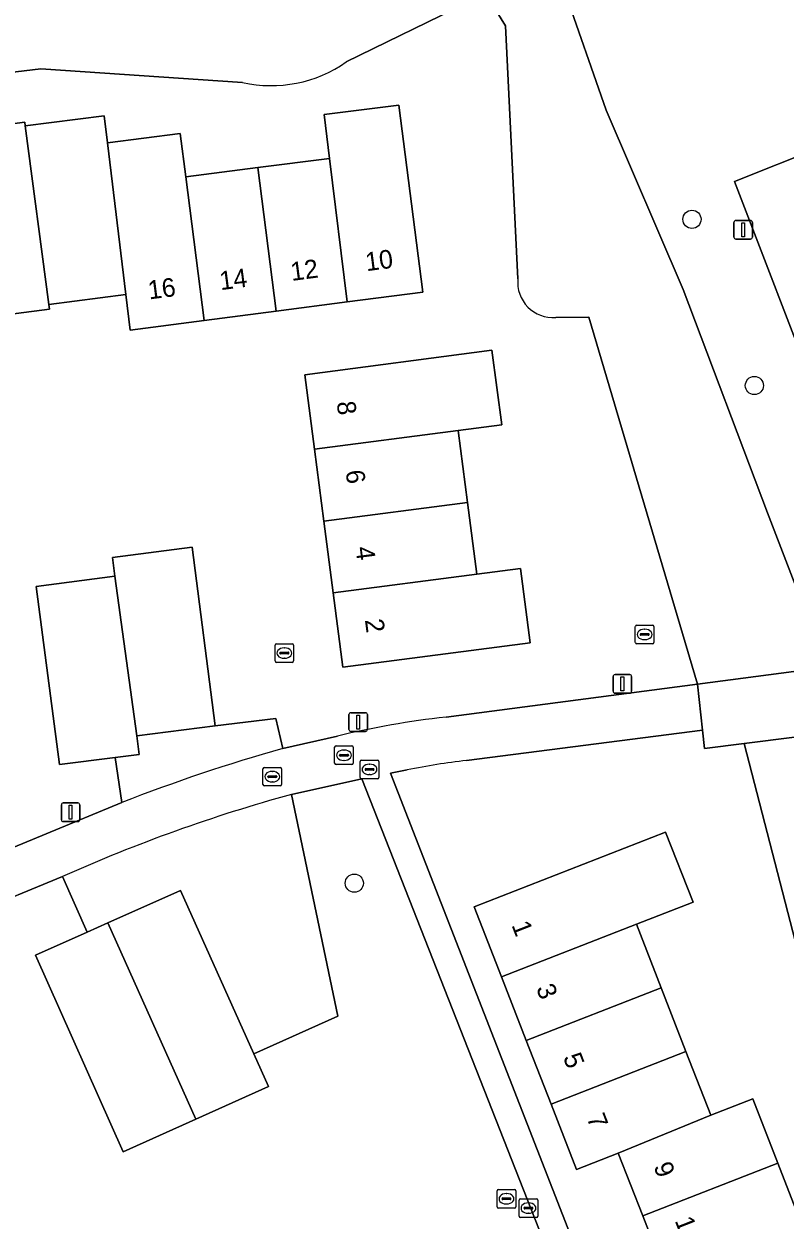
# Model space of a CAD drawing. Extents: x 159451 to 160664, y 388402 to 389723.
# Drawn here: x 159545.2 to 159586.1, y 389229 to 389293.3 of the extents above; entities that cross this region are included whole.
import ezdxf

# ---------------------------------------------------------------- set-up
doc = ezdxf.new("R2010")
doc.units = 0
for name, color, linetype in [('IMGEO_Boom', 7, 'Continuous'), ('IMGEO_Bouwland', 7, 'Continuous'), ('IMGEO_Groenvoorziening', 7, 'Continuous'), ('IMGEO_Lichtmast', 7, 'Continuous'), ('IMGEO_Meer_plas_ven_vijver', 7, 'Continuous'), ('IMGEO_Pand', 7, 'Continuous'), ('IMGEO_Pand_nummerreeks', 7, 'Continuous'), ('IMGEO_Parkeervlak_halfverhard', 7, 'Continuous'), ('IMGEO_Rijbaan_lokaal_gesloten', 7, 'Continuous'), ('IMGEO_Rijbaan_lokaal_halfverhard', 7, 'Continuous'), ('IMGEO_Rioolput', 7, 'Continuous')]:
    doc.layers.add(name, color=color, linetype=linetype)

msp = doc.modelspace()

# ---------------------------------------------------------------- linework, layer by layer
at = {"layer": 'IMGEO_Boom'}
for centre in [(159581.107, 389282.768), (159584.465, 389273.835), (159562.963, 389247.093)]:
    msp.add_circle(centre, 0.489, dxfattribs=at)
at = {"layer": 'IMGEO_Bouwland'}
for points in [[(159590.332, 389238.414), (159588.958, 389238.151), (159588.252, 389238.537), (159587.915, 389239.139), (159583.906, 389254.592), (159581.78, 389254.325), (159581.675, 389255.309), (159568.993, 389253.682)], [(159580.373, 389208.403), (159573.107, 389227.927), (159563.374, 389252.707), (159559.597, 389251.864), (159562.085, 389239.938), (159557.562, 389237.923), (159558.351, 389236.161), (159554.447, 389234.413), (159550.543, 389232.664), (159545.842, 389243.23), (159548.614, 389244.465), (159547.283, 389247.447), (159522.997, 389237.416), (159523.334, 389236.494), (159515.988, 389233.475), (159514.682, 389236.714), (159522.027, 389239.718), (159536.816, 389245.805), (159535.285, 389249.699)], [(159565.813, 389253.186), (159564.916, 389253.004), (159575.523, 389225.793), (159580.698, 389211.752)]]:
    msp.add_lwpolyline(points, dxfattribs=at)
msp.add_lwpolyline([(159585.725, 389232.05), (159587.076, 389228.593), (159588.427, 389225.136), (159591.484, 389226.33), (159592.944, 389222.587), (159582.637, 389218.552), (159581.17, 389222.301), (159579.818, 389225.756), (159578.465, 389229.213), (159577.145, 389232.586), (159574.908, 389231.714), (159573.541, 389235.222), (159572.208, 389238.644), (159570.876, 389242.061), (159569.411, 389245.821), (159579.696, 389249.831), (159581.176, 389246.078), (159578.122, 389244.887), (159579.454, 389241.465), (159580.787, 389238.042), (159582.119, 389234.62), (159584.374, 389235.507)], close=True, dxfattribs=at)
msp.add_arc((159573.115, 389216.814), 37.098, 96.37912, 101.35142, dxfattribs=at)
at = {"layer": 'IMGEO_Groenvoorziening'}
for points in [[(159574.217, 389295.171), (159576.492, 389288.625), (159580.643, 389278.999), (159585.177, 389266.997), (159588.35, 389258.709)], [(159571.755, 389279.564), (159571.085, 389293.162), (159570.386, 389294.298), (159569.066, 389294.418), (159562.535, 389291.222)], [(159556.966, 389290.126), (159546.129, 389290.863), (159532.239, 389289.197)], [(159541.295, 389287.473), (159545.256, 389287.981), (159545.281, 389287.787), (159549.518, 389288.329), (159549.707, 389286.878), (159553.612, 389287.385), (159553.913, 389285.047), (159557.776, 389285.546), (159561.639, 389286.044), (159561.351, 389288.395), (159565.365, 389288.906), (159566.652, 389278.858), (159562.584, 389278.33), (159558.771, 389277.834), (159554.906, 389277.332), (159550.926, 389276.815), (159550.68, 389278.733), (159546.558, 389278.199), (159546.592, 389277.935), (159542.577, 389277.414)], [(159587.925, 389273.015), (159583.387, 389284.803), (159588.068, 389286.657)], [(159567.894, 389256.022), (159581.411, 389257.784), (159575.559, 389277.502), (159573.786, 389277.496)], [(159537.657, 389247.809), (159538.251, 389246.377), (159550.467, 389251.425), (159550.122, 389253.843), (159547.128, 389253.464), (159545.873, 389263.038), (159550.103, 389263.588), (159549.974, 389264.586), (159554.246, 389265.142), (159555.492, 389255.556), (159558.754, 389255.947), (159559.116, 389254.331), (159562.054, 389254.997)]]:
    msp.add_lwpolyline(points, dxfattribs=at)
msp.add_lwpolyline([(159570.891, 389271.725), (159568.539, 389271.414), (159569.046, 389267.555), (159569.552, 389263.705), (159571.892, 389264.011), (159572.415, 389260.004), (159562.352, 389258.693), (159561.831, 389262.703), (159561.332, 389266.553), (159560.83, 389270.413), (159560.311, 389274.413), (159570.362, 389275.731)], close=True, dxfattribs=at)
for centre, radius, start, end in [((159558.519, 389296.933), 6.981, 257.14877, 305.1187), ((159573.634, 389279.378), 1.888, 174.357, 274.60866), ((159573.278, 389208.199), 48.125, 96.42296, 103.48665)]:
    msp.add_arc(centre, radius, start, end, dxfattribs=at)
at = {"layer": 'IMGEO_Lichtmast'}
for p, q in [((159583.368, 389281.803), (159583.368, 389282.603)), ((159583.368, 389282.603), (159583.368, 389281.803)), ((159583.468, 389282.703), (159584.258, 389282.703)), ((159584.258, 389282.703), (159583.468, 389282.703)), ((159584.358, 389282.603), (159584.358, 389281.803)), ((159584.358, 389281.803), (159584.358, 389282.603)), ((159584.258, 389281.703), (159583.468, 389281.703)), ((159583.468, 389281.703), (159584.258, 389281.703)), ((159576.874, 389257.405), (159576.874, 389258.205)), ((159576.874, 389258.205), (159576.874, 389257.405)), ((159576.974, 389258.305), (159577.764, 389258.305)), ((159577.764, 389258.305), (159576.974, 389258.305)), ((159577.864, 389258.205), (159577.864, 389257.405)), ((159577.864, 389257.405), (159577.864, 389258.205)), ((159577.764, 389257.305), (159576.974, 389257.305)), ((159576.974, 389257.305), (159577.764, 389257.305)), ((159562.679, 389255.352), (159562.679, 389256.152)), ((159562.679, 389256.152), (159562.679, 389255.352)), ((159562.779, 389256.252), (159563.569, 389256.252)), ((159563.569, 389256.252), (159562.779, 389256.252)), ((159563.669, 389256.152), (159563.669, 389255.352)), ((159563.669, 389255.352), (159563.669, 389256.152)), ((159563.569, 389255.252), (159562.779, 389255.252)), ((159562.779, 389255.252), (159563.569, 389255.252)), ((159547.225, 389250.504), (159547.225, 389251.304)), ((159547.225, 389251.304), (159547.225, 389250.504)), ((159547.325, 389251.404), (159548.115, 389251.404)), ((159548.115, 389251.404), (159547.325, 389251.404)), ((159548.215, 389251.304), (159548.215, 389250.504)), ((159548.215, 389250.504), (159548.215, 389251.304)), ((159548.115, 389250.404), (159547.325, 389250.404)), ((159547.325, 389250.404), (159548.115, 389250.404))]:
    msp.add_line(p, q, dxfattribs=at)
for points in [[(159583.788, 389282.578), (159583.938, 389282.578), (159583.938, 389281.828), (159583.788, 389281.828), (159583.788, 389282.578)], [(159577.294, 389258.18), (159577.444, 389258.18), (159577.444, 389257.43), (159577.294, 389257.43), (159577.294, 389258.18)], [(159563.099, 389256.127), (159563.249, 389256.127), (159563.249, 389255.377), (159563.099, 389255.377), (159563.099, 389256.127)], [(159547.645, 389251.279), (159547.795, 389251.279), (159547.795, 389250.529), (159547.645, 389250.529), (159547.645, 389251.279)]]:
    msp.add_lwpolyline(points, dxfattribs=at)
for centre, start, end in [((159583.468, 389282.603), 90, 180), ((159583.468, 389282.603), 90, 180), ((159584.258, 389282.603), 0, 90), ((159584.258, 389282.603), 360, 90), ((159583.468, 389281.803), 180, 270), ((159583.468, 389281.803), 180, 270), ((159584.258, 389281.803), 270, 0), ((159584.258, 389281.803), 270, 0), ((159576.974, 389258.205), 90, 180), ((159576.974, 389258.205), 90, 180), ((159577.764, 389258.205), 0, 90), ((159577.764, 389258.205), 360, 90), ((159576.974, 389257.405), 180, 270), ((159576.974, 389257.405), 180, 270), ((159577.764, 389257.405), 270, 0), ((159577.764, 389257.405), 270, 0), ((159562.779, 389256.152), 90, 180), ((159562.779, 389256.152), 90, 180), ((159563.569, 389256.152), 0, 90), ((159563.569, 389256.152), 360, 90), ((159562.779, 389255.352), 180, 270), ((159562.779, 389255.352), 180, 270), ((159563.569, 389255.352), 270, 0), ((159563.569, 389255.352), 270, 0), ((159547.325, 389251.304), 90, 180), ((159547.325, 389251.304), 90, 180), ((159548.115, 389251.304), 0, 90), ((159548.115, 389251.304), 360, 90), ((159547.325, 389250.504), 180, 270), ((159547.325, 389250.504), 180, 270), ((159548.115, 389250.504), 270, 0), ((159548.115, 389250.504), 270, 0)]:
    msp.add_arc(centre, 0.1, start, end, dxfattribs=at)
at = {"layer": 'IMGEO_Meer_plas_ven_vijver'}
for points in [[(159581.411, 389257.784), (159588.35, 389258.709), (159585.177, 389266.997), (159580.643, 389278.999), (159576.492, 389288.625), (159574.217, 389295.171)], [(159562.535, 389291.222), (159569.066, 389294.418), (159570.386, 389294.298), (159571.085, 389293.162), (159571.755, 389279.564)], [(159532.239, 389289.197), (159546.129, 389290.863), (159556.966, 389290.126)], [(159573.786, 389277.496), (159575.559, 389277.502), (159581.411, 389257.784)], [(159589.472, 389255.292), (159583.906, 389254.592), (159587.915, 389239.139), (159588.252, 389238.537), (159588.958, 389238.151), (159590.332, 389238.414), (159596.055, 389223.424)]]:
    msp.add_lwpolyline(points, dxfattribs=at)
for centre, radius, start, end in [((159558.519, 389296.933), 6.981, 257.14877, 305.1187), ((159573.634, 389279.378), 1.888, 174.357, 274.60866)]:
    msp.add_arc(centre, radius, start, end, dxfattribs=at)
at = {"layer": 'IMGEO_Pand'}
for points in [[(159565.365, 389288.906), (159561.351, 389288.395), (159561.639, 389286.044), (159562.584, 389278.33), (159566.652, 389278.858)], [(159545.281, 389287.787), (159545.256, 389287.981), (159541.295, 389287.473), (159541.594, 389285.127), (159542.577, 389277.414), (159546.592, 389277.935), (159546.558, 389278.199)], [(159549.707, 389286.878), (159549.518, 389288.329), (159545.281, 389287.787), (159546.558, 389278.199), (159550.68, 389278.733)], [(159553.913, 389285.047), (159553.612, 389287.385), (159549.707, 389286.878), (159550.68, 389278.733), (159550.926, 389276.815), (159554.906, 389277.332)], [(159561.639, 389286.044), (159557.776, 389285.546), (159558.771, 389277.834), (159562.584, 389278.33)], [(159557.776, 389285.546), (159553.913, 389285.047), (159554.906, 389277.332), (159558.771, 389277.834)], [(159570.362, 389275.731), (159560.311, 389274.413), (159560.83, 389270.413), (159568.539, 389271.414), (159570.891, 389271.725)], [(159568.539, 389271.414), (159560.83, 389270.413), (159561.332, 389266.553), (159569.046, 389267.555)], [(159569.046, 389267.555), (159561.332, 389266.553), (159561.831, 389262.703), (159569.552, 389263.705)], [(159554.246, 389265.142), (159549.974, 389264.586), (159550.103, 389263.588), (159551.271, 389255.006), (159555.492, 389255.556)], [(159550.103, 389263.588), (159545.873, 389263.038), (159547.128, 389253.464), (159550.122, 389253.843), (159551.405, 389254.005), (159551.271, 389255.006)], [(159571.892, 389264.011), (159569.552, 389263.705), (159561.831, 389262.703), (159562.352, 389258.693), (159572.415, 389260.004)], [(159581.176, 389246.078), (159579.696, 389249.831), (159569.411, 389245.821), (159570.876, 389242.061), (159578.122, 389244.887)], [(159553.631, 389246.699), (159549.724, 389244.959), (159554.447, 389234.413), (159558.351, 389236.161), (159557.562, 389237.923)], [(159549.724, 389244.959), (159548.614, 389244.465), (159545.842, 389243.23), (159550.543, 389232.664), (159554.447, 389234.413)], [(159579.454, 389241.465), (159578.122, 389244.887), (159570.876, 389242.061), (159572.208, 389238.644)], [(159580.787, 389238.042), (159579.454, 389241.465), (159572.208, 389238.644), (159573.541, 389235.222)], [(159582.119, 389234.62), (159580.787, 389238.042), (159573.541, 389235.222), (159574.908, 389231.714), (159577.145, 389232.586)], [(159585.725, 389232.05), (159584.374, 389235.507), (159582.119, 389234.62), (159577.145, 389232.586), (159578.465, 389229.213)], [(159585.725, 389232.05), (159578.465, 389229.213), (159579.818, 389225.756), (159587.076, 389228.593)]]:
    msp.add_lwpolyline(points, close=True, dxfattribs=at)
at = {"layer": 'IMGEO_Parkeervlak_halfverhard'}
msp.add_lwpolyline([(159588.068, 389286.657), (159583.387, 389284.803), (159587.925, 389273.015), (159592.686, 389274.813)], close=True, dxfattribs=at)
at = {"layer": 'IMGEO_Rijbaan_lokaal_gesloten'}
msp.add_lwpolyline([(159588.35, 389258.709), (159581.411, 389257.784), (159581.675, 389255.309), (159581.78, 389254.325), (159583.906, 389254.592), (159589.472, 389255.292), (159589.73, 389255.325)], close=True, dxfattribs=at)
for points in [[(159568.993, 389253.682), (159581.675, 389255.309), (159581.411, 389257.784), (159567.894, 389256.022)], [(159562.054, 389254.997), (159559.116, 389254.331)], [(159559.597, 389251.864), (159563.374, 389252.707), (159573.107, 389227.927), (159580.373, 389208.403)], [(159580.698, 389211.752), (159575.523, 389225.793), (159564.916, 389253.004), (159565.813, 389253.186)], [(159550.467, 389251.425), (159538.251, 389246.377), (159537.657, 389247.809)], [(159535.285, 389249.699), (159536.816, 389245.805), (159522.027, 389239.718), (159522.997, 389237.416), (159547.283, 389247.447)]]:
    msp.add_lwpolyline(points, dxfattribs=at)
for centre, radius, start, end in [((159573.278, 389208.199), 48.125, 96.42296, 103.48665), ((159584.912, 389163.233), 94.68, 105.81014, 111.33379), ((159573.115, 389216.814), 37.098, 96.37912, 101.35142), ((159582.261, 389169.306), 85.612, 105.35087, 114.11468)]:
    msp.add_arc(centre, radius, start, end, dxfattribs=at)
at = {"layer": 'IMGEO_Rijbaan_lokaal_halfverhard'}
for points in [[(159559.116, 389254.331), (159558.754, 389255.947), (159555.492, 389255.556), (159551.271, 389255.006), (159551.405, 389254.005), (159550.122, 389253.843), (159550.467, 389251.425)], [(159547.283, 389247.447), (159548.614, 389244.465), (159549.724, 389244.959), (159553.631, 389246.699), (159557.562, 389237.923), (159562.085, 389239.938), (159559.597, 389251.864)]]:
    msp.add_lwpolyline(points, dxfattribs=at)
for centre, radius, start, end in [((159584.912, 389163.233), 94.68, 105.81014, 111.33379), ((159582.261, 389169.306), 85.612, 105.35087, 114.11468)]:
    msp.add_arc(centre, radius, start, end, dxfattribs=at)
at = {"layer": 'IMGEO_Rioolput'}
for p, q in [((159578.141, 389260.959), (159578.993, 389260.959)), ((159578.066, 389260.033), (159578.066, 389260.885)), ((159578.325, 389260.453), (159578.325, 389260.465)), ((159578.763, 389260.416), (159578.365, 389260.416)), ((159578.368, 389260.502), (159578.766, 389260.502)), ((159578.554, 389260.739), (159578.579, 389260.739)), ((159578.809, 389260.465), (159578.809, 389260.453)), ((159579.067, 389260.885), (159579.067, 389260.033)), ((159558.705, 389259.033), (159558.705, 389259.885)), ((159558.78, 389259.959), (159559.632, 389259.959)), ((159559.193, 389259.739), (159559.218, 389259.739)), ((159559.706, 389259.885), (159559.706, 389259.033)), ((159578.993, 389259.959), (159578.141, 389259.959)), ((159578.577, 389260.179), (159578.552, 389260.179)), ((159558.964, 389259.453), (159558.964, 389259.465)), ((159559.402, 389259.416), (159559.004, 389259.416)), ((159559.007, 389259.502), (159559.405, 389259.502)), ((159559.216, 389259.179), (159559.191, 389259.179)), ((159559.448, 389259.465), (159559.448, 389259.453)), ((159559.632, 389258.959), (159558.78, 389258.959)), ((159561.908, 389253.543), (159561.908, 389254.395)), ((159561.983, 389254.469), (159562.835, 389254.469)), ((159562.167, 389253.963), (159562.167, 389253.975)), ((159562.605, 389253.926), (159562.207, 389253.926)), ((159562.21, 389254.012), (159562.608, 389254.012)), ((159562.396, 389254.249), (159562.421, 389254.249)), ((159562.651, 389253.975), (159562.651, 389253.963)), ((159562.909, 389254.395), (159562.909, 389253.543)), ((159558.058, 389252.391), (159558.058, 389253.243)), ((159558.133, 389253.317), (159558.985, 389253.317)), ((159559.059, 389253.243), (159559.059, 389252.391)), ((159562.835, 389253.469), (159561.983, 389253.469)), ((159562.419, 389253.689), (159562.394, 389253.689)), ((159563.282, 389252.779), (159563.282, 389253.631)), ((159563.357, 389253.705), (159564.209, 389253.705)), ((159563.541, 389253.199), (159563.541, 389253.211)), ((159563.584, 389253.248), (159563.982, 389253.248)), ((159563.77, 389253.485), (159563.795, 389253.485)), ((159564.025, 389253.211), (159564.025, 389253.199)), ((159564.283, 389253.631), (159564.283, 389252.779)), ((159558.317, 389252.811), (159558.317, 389252.823)), ((159558.755, 389252.774), (159558.357, 389252.774)), ((159558.36, 389252.86), (159558.758, 389252.86)), ((159558.546, 389253.097), (159558.571, 389253.097)), ((159558.801, 389252.823), (159558.801, 389252.811)), ((159564.209, 389252.705), (159563.357, 389252.705)), ((159563.979, 389253.162), (159563.581, 389253.162)), ((159563.793, 389252.925), (159563.768, 389252.925)), ((159558.985, 389252.317), (159558.133, 389252.317)), ((159558.569, 389252.537), (159558.544, 389252.537)), ((159570.642, 389229.707), (159570.642, 389230.559)), ((159570.717, 389230.633), (159571.569, 389230.633)), ((159570.901, 389230.127), (159570.901, 389230.139)), ((159571.339, 389230.09), (159570.941, 389230.09)), ((159570.944, 389230.176), (159571.342, 389230.176)), ((159571.13, 389230.413), (159571.155, 389230.413)), ((159571.385, 389230.139), (159571.385, 389230.127)), ((159571.643, 389230.559), (159571.643, 389229.707)), ((159571.823, 389229.206), (159571.823, 389230.058)), ((159571.898, 389230.132), (159572.75, 389230.132)), ((159572.824, 389230.058), (159572.824, 389229.206)), ((159571.569, 389229.633), (159570.717, 389229.633)), ((159571.153, 389229.853), (159571.128, 389229.853)), ((159572.082, 389229.626), (159572.082, 389229.638)), ((159572.52, 389229.589), (159572.122, 389229.589)), ((159572.125, 389229.675), (159572.523, 389229.675)), ((159572.311, 389229.912), (159572.336, 389229.912)), ((159572.566, 389229.638), (159572.566, 389229.626)), ((159572.75, 389229.132), (159571.898, 389229.132)), ((159572.334, 389229.352), (159572.309, 389229.352))]:
    msp.add_line(p, q, dxfattribs=at)
for points in [[(159578.141, 389260.959), (159578.993, 389260.959)], [(159578.066, 389260.033), (159578.066, 389260.885)], [(159579.067, 389260.885), (159579.067, 389260.033)], [(159558.705, 389259.033), (159558.705, 389259.885)], [(159558.78, 389259.959), (159559.632, 389259.959)], [(159559.706, 389259.885), (159559.706, 389259.033)], [(159578.993, 389259.959), (159578.141, 389259.959)], [(159559.632, 389258.959), (159558.78, 389258.959)], [(159561.908, 389253.543), (159561.908, 389254.395)], [(159561.983, 389254.469), (159562.835, 389254.469)], [(159562.909, 389254.395), (159562.909, 389253.543)], [(159558.058, 389252.391), (159558.058, 389253.243)], [(159558.133, 389253.317), (159558.985, 389253.317)], [(159559.059, 389253.243), (159559.059, 389252.391)], [(159562.835, 389253.469), (159561.983, 389253.469)], [(159563.282, 389252.779), (159563.282, 389253.631)], [(159563.357, 389253.705), (159564.209, 389253.705)], [(159564.283, 389253.631), (159564.283, 389252.779)], [(159564.209, 389252.705), (159563.357, 389252.705)], [(159558.985, 389252.317), (159558.133, 389252.317)], [(159570.642, 389229.707), (159570.642, 389230.559)], [(159570.717, 389230.633), (159571.569, 389230.633)], [(159571.643, 389230.559), (159571.643, 389229.707)], [(159571.823, 389229.206), (159571.823, 389230.058)], [(159571.898, 389230.132), (159572.75, 389230.132)], [(159572.824, 389230.058), (159572.824, 389229.206)], [(159571.569, 389229.633), (159570.717, 389229.633)], [(159572.75, 389229.132), (159571.898, 389229.132)]]:
    msp.add_lwpolyline(points, dxfattribs=at)
for centre, radius, start, end in [((159578.143, 389260.883), 0.0765, 91.55205, 178.44795), ((159578.143, 389260.883), 0.0765, 91.55205, 178.44795), ((159578.991, 389260.883), 0.0765, 1.55205, 88.44795), ((159578.991, 389260.883), 0.0765, 1.55205, 88.44795), ((159578.365, 389260.462), 0.0403, 85.87752, 175.75265), ((159578.362, 389260.452), 0.0366, 178.93798, 274.71019), ((159578.766, 389260.459), 0.043, 264.86636, 352.45326), ((159578.77, 389260.464), 0.0386, 1.73085, 96.63898), ((159558.782, 389259.883), 0.0765, 91.55205, 178.44795), ((159558.782, 389259.883), 0.0765, 91.55205, 178.44795), ((159559.63, 389259.883), 0.0765, 1.55205, 88.44795), ((159559.63, 389259.883), 0.0765, 1.55205, 88.44795), ((159578.143, 389260.035), 0.0765, 181.55205, 268.44795), ((159578.143, 389260.035), 0.0765, 181.55205, 268.44795), ((159578.991, 389260.035), 0.0765, 271.55205, 358.44795), ((159578.991, 389260.035), 0.0765, 271.55205, 358.44795), ((159558.782, 389259.035), 0.0765, 181.55205, 268.44795), ((159558.782, 389259.035), 0.0765, 181.55205, 268.44795), ((159559.004, 389259.462), 0.0403, 85.87752, 175.75265), ((159559.001, 389259.452), 0.0366, 178.93798, 274.71019), ((159559.405, 389259.459), 0.043, 264.86636, 352.45326), ((159559.409, 389259.464), 0.0386, 1.73085, 96.63898), ((159559.63, 389259.035), 0.0765, 271.55205, 358.44795), ((159559.63, 389259.035), 0.0765, 271.55205, 358.44795), ((159561.985, 389254.393), 0.0765, 91.55205, 178.44795), ((159561.985, 389254.393), 0.0765, 91.55205, 178.44795), ((159562.207, 389253.972), 0.0403, 85.87752, 175.75265), ((159562.204, 389253.962), 0.0366, 178.93798, 274.71019), ((159562.608, 389253.969), 0.043, 264.86636, 352.45326), ((159562.612, 389253.974), 0.0386, 1.73085, 96.63898), ((159562.833, 389254.393), 0.0765, 1.55205, 88.44795), ((159562.833, 389254.393), 0.0765, 1.55205, 88.44795), ((159558.135, 389253.241), 0.0765, 91.55205, 178.44795), ((159558.135, 389253.241), 0.0765, 91.55205, 178.44795), ((159558.983, 389253.241), 0.0765, 1.55205, 88.44795), ((159558.983, 389253.241), 0.0765, 1.55205, 88.44795), ((159561.985, 389253.545), 0.0765, 181.55205, 268.44795), ((159561.985, 389253.545), 0.0765, 181.55205, 268.44795), ((159562.833, 389253.545), 0.0765, 271.55205, 358.44795), ((159562.833, 389253.545), 0.0765, 271.55205, 358.44795), ((159563.359, 389253.629), 0.0765, 91.55205, 178.44795), ((159563.359, 389253.629), 0.0765, 91.55205, 178.44795), ((159563.581, 389253.208), 0.0403, 85.87752, 175.75265), ((159563.578, 389253.198), 0.0366, 178.93798, 274.71019), ((159563.982, 389253.205), 0.043, 264.86636, 352.45326), ((159563.986, 389253.21), 0.0386, 1.73085, 96.63898), ((159564.207, 389253.629), 0.0765, 1.55205, 88.44795), ((159564.207, 389253.629), 0.0765, 1.55205, 88.44795), ((159558.357, 389252.82), 0.0403, 85.87752, 175.75265), ((159558.354, 389252.81), 0.0366, 178.93798, 274.71019), ((159558.758, 389252.817), 0.043, 264.86636, 352.45326), ((159558.762, 389252.822), 0.0386, 1.73085, 96.63898), ((159563.359, 389252.781), 0.0765, 181.55205, 268.44795), ((159563.359, 389252.781), 0.0765, 181.55205, 268.44795), ((159564.207, 389252.781), 0.0765, 271.55205, 358.44795), ((159564.207, 389252.781), 0.0765, 271.55205, 358.44795), ((159558.135, 389252.393), 0.0765, 181.55205, 268.44795), ((159558.135, 389252.393), 0.0765, 181.55205, 268.44795), ((159558.983, 389252.393), 0.0765, 271.55205, 358.44795), ((159558.983, 389252.393), 0.0765, 271.55205, 358.44795), ((159570.719, 389230.557), 0.0765, 91.55205, 178.44795), ((159570.719, 389230.557), 0.0765, 91.55205, 178.44795), ((159570.941, 389230.136), 0.0403, 85.87752, 175.75265), ((159570.938, 389230.126), 0.0366, 178.93798, 274.71019), ((159571.342, 389230.133), 0.043, 264.86636, 352.45326), ((159571.346, 389230.138), 0.0386, 1.73085, 96.63898), ((159571.567, 389230.557), 0.0765, 1.55205, 88.44795), ((159571.567, 389230.557), 0.0765, 1.55205, 88.44795), ((159571.9, 389230.056), 0.0765, 91.55205, 178.44795), ((159571.9, 389230.056), 0.0765, 91.55205, 178.44795), ((159572.748, 389230.056), 0.0765, 1.55205, 88.44795), ((159572.748, 389230.056), 0.0765, 1.55205, 88.44795), ((159570.719, 389229.709), 0.0765, 181.55205, 268.44795), ((159570.719, 389229.709), 0.0765, 181.55205, 268.44795), ((159571.567, 389229.709), 0.0765, 271.55205, 358.44795), ((159571.567, 389229.709), 0.0765, 271.55205, 358.44795), ((159572.122, 389229.635), 0.0403, 85.87752, 175.75265), ((159572.119, 389229.625), 0.0366, 178.93798, 274.71019), ((159572.523, 389229.632), 0.043, 264.86636, 352.45326), ((159572.527, 389229.637), 0.0386, 1.73085, 96.63898), ((159571.9, 389229.208), 0.0765, 181.55205, 268.44795), ((159571.9, 389229.208), 0.0765, 181.55205, 268.44795), ((159572.748, 389229.208), 0.0765, 271.55205, 358.44795), ((159572.748, 389229.208), 0.0765, 271.55205, 358.44795)]:
    msp.add_arc(centre, radius, start, end, dxfattribs=at)
for centre, major_axis, ratio, start_param, end_param in [((159578.553, 389260.459), (-0.387, 0.002), 0.722429, 4.712389, 7.853982), ((159578.578, 389260.459), (-0.39, 0.002), 0.717154, 1.570796, 4.712389), ((159559.192, 389259.459), (-0.387, 0.002), 0.722429, 4.712389, 7.853982), ((159559.217, 389259.459), (-0.39, 0.002), 0.717154, 1.570796, 4.712389), ((159562.395, 389253.969), (-0.387, 0.002), 0.722429, 4.712389, 7.853982), ((159562.42, 389253.969), (-0.39, 0.002), 0.717154, 1.570796, 4.712389), ((159563.769, 389253.205), (-0.387, 0.002), 0.722429, 4.712389, 7.853982), ((159563.794, 389253.205), (-0.39, 0.002), 0.717154, 1.570796, 4.712389), ((159558.545, 389252.817), (-0.387, 0.002), 0.722429, 4.712389, 7.853982), ((159558.57, 389252.817), (-0.39, 0.002), 0.717154, 1.570796, 4.712389), ((159571.129, 389230.133), (-0.387, 0.002), 0.722429, 4.712389, 7.853982), ((159571.154, 389230.133), (-0.39, 0.002), 0.717154, 1.570796, 4.712389), ((159572.31, 389229.632), (-0.387, 0.002), 0.722429, 4.712389, 7.853982), ((159572.335, 389229.632), (-0.39, 0.002), 0.717154, 1.570796, 4.712389)]:
    msp.add_ellipse(centre, major_axis=major_axis, ratio=ratio, start_param=start_param, end_param=end_param, dxfattribs=at)

# ---------------------------------------------------------------- texts
at = {"layer": 'IMGEO_Pand_nummerreeks'}
for s, rotation, p in [('10', 7.40261, (159563.621, 389279.977)), ('12', 7.40261, (159559.603, 389279.455)), ('16', 7.40261, (159551.942, 389278.46)), ('14', 7.40261, (159555.784, 389278.959)), ('8', 277.39667, (159562.015, 389272.937)), ('6', 277.39667, (159562.495, 389269.241)), ('4', 277.39667, (159563.028, 389265.132)), ('2', 277.39667, (159563.533, 389261.242)), ('1', 291.2909, (159571.403, 389244.841)), ('3', 291.2909, (159572.722, 389241.455)), ('5', 291.2909, (159574.169, 389237.742)), ('7', 291.2909, (159575.436, 389234.49)), ('9', 291.37112, (159579.033, 389231.878)), ('11', 291.37112, (159580.175, 389228.96))]:
    msp.add_text(s, height=1, rotation=rotation, dxfattribs=at).set_placement(p)

doc.saveas('drawing.dxf')
